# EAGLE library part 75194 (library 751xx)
75xxx DEVICE
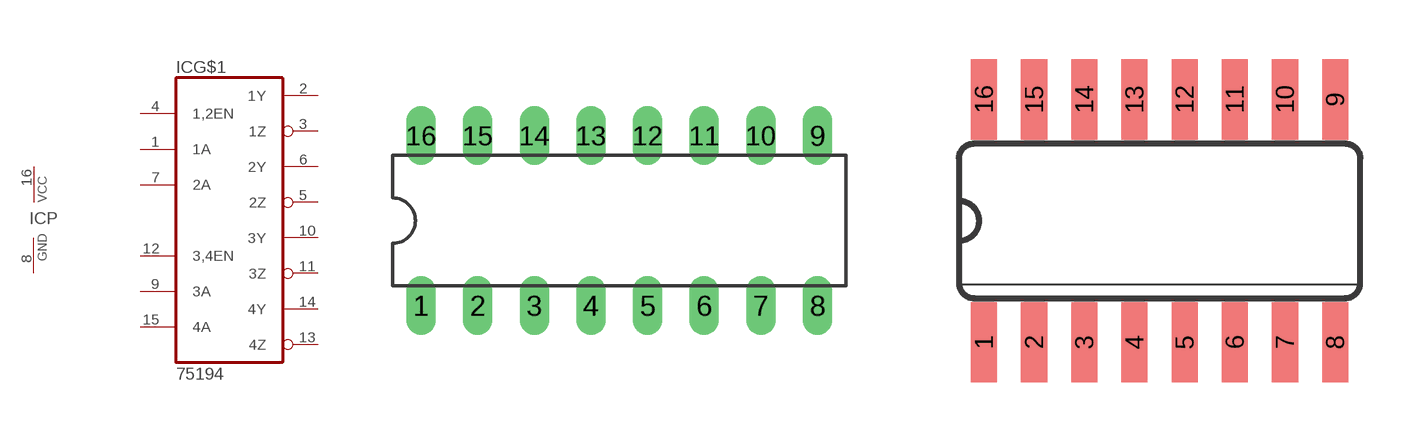
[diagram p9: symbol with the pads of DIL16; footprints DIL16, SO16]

Designator prefix IC; gates G$1=75194 P=PWRN

## 75194P  [DIL16]
1  G$1:1A  in
2  G$1:1Y  hiz
3  G$1:1Z  hiz
4  G$1:1,2EN  in
5  G$1:2Z  hiz
6  G$1:2Y  hiz
7  G$1:2A  in
8  P:GND  pwr
9  G$1:3A  in
10  G$1:3Y  hiz
11  G$1:3Z  hiz
12  G$1:3,4EN  in
13  G$1:4Z  hiz
14  G$1:4Y  hiz
15  G$1:4A  in
16  P:VCC  pwr

## 75194SO  [SO16]
Pads as for DIL16

## Footprint DIL16 (pad centres in mm)
Dual In Line Package
drill 0.813 long: 1 -8.89,-3.81; 2 -6.35,-3.81; 3 -3.81,-3.81; 4 -1.27,-3.81; 5 1.27,-3.81; 6 3.81,-3.81; 7 6.35,-3.81; 8 8.89,-3.81; 9 8.89,3.81; 10 6.35,3.81; 11 3.81,3.81; 12 1.27,3.81; 13 -1.27,3.81; 14 -3.81,3.81; 15 -6.35,3.81; 16 -8.89,3.81

## Footprint SO16 (pad centres in mm)
Small Outline package 150 mil
smd 0.66 x 2.032: 1 -4.445,-3.073; 2 -3.175,-3.073; 3 -1.905,-3.073; 4 -0.635,-3.073; 5 0.635,-3.073; 6 1.905,-3.073; 7 3.175,-3.073; 8 4.445,-3.073; 9 4.445,3.073; 10 3.175,3.073; 11 1.905,3.073; 12 0.635,3.073; 13 -0.635,3.073; 14 -1.905,3.073; 15 -3.175,3.073; 16 -4.445,3.073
